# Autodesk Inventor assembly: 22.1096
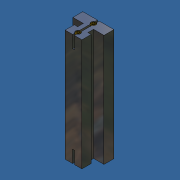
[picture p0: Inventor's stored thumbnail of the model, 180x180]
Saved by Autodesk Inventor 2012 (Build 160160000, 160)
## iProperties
Created: 2007-06
Part Number: 22.1096
Document SubType Name: Assembly
Designer: Andy Moles
Description: SLIDE RAIL LN-S
Vendor: S
Author: Andy Moles
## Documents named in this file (5)
- C:\Andys Backup Data\ANDY'S INVENTOR\INVENTOR LIBRARIES\PARTS LIBRARY\COMPONENTS LG\22.1096 SLIDE RAIL LN-S.iam
- C:\Andys Backup Data\ANDY'S INVENTOR\INVENTOR LIBRARIES\PARTS LIBRARY\COMPONENTS LG\SUBCOMPONENTS\22.1096_1 SLIDE RAIL LN-S SLIDE BAR.ipt
- C:\Andys Backup Data\ANDY'S INVENTOR\INVENTOR LIBRARIES\PARTS LIBRARY\COMPONENTS LG\SUBCOMPONENTS\22.1096 SLIDE RAIL LN-S THREAD INSERT.ipt
- C:\Andys Backup Data\ANDY'S INVENTOR\INVENTOR LIBRARIES\PARTS LIBRARY\FASTENING ELEMENTS\SET SCREWS\21.1314 M4x8 SET SCREW POINTED.IPT
- C:\Andys Backup Data\ANDY'S INVENTOR\INVENTOR LIBRARIES\PARTS LIBRARY\FASTENING ELEMENTS\SCREWS CAP\21.1229 M4x12.ipt
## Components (9 placed, 4 different names)
1. 22.1096_1 SLIDE RAIL LN-S SLIDE BAR:1 — Insert:2, Insert:3, Insert:4, Insert:5, Insert:6, Insert:9
2. 22.1096 SLIDE RAIL LN-S THREAD INSERT:1 — Insert:2, Insert:8
3. 22.1096 SLIDE RAIL LN-S THREAD INSERT:2 — Insert:7, Insert:9
4. 21.1314 M4X8 SET SCREW CONE POINT DIN 914:1 — Insert:3
5. 21.1314 M4X8 SET SCREW CONE POINT DIN 914:2 — Insert:4
6. 21.1314 M4X8 SET SCREW CONE POINT DIN 914:3 — Insert:5
7. 21.1314 M4X8 SET SCREW CONE POINT DIN 914:4 — Insert:6
8. 21.1229 SHCS M4X12 DIN 7984:1 — Insert:7
9. 21.1229 SHCS M4X12 DIN 7984:2 — Insert:8
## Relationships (8: Insert 8)
- Insert:2: 22.1096_1 SLIDE RAIL LN-S SLIDE BAR:1 ↔ 22.1096 SLIDE RAIL LN-S THREAD INSERT:1
- Insert:3: 22.1096_1 SLIDE RAIL LN-S SLIDE BAR:1 ↔ 21.1314 M4X8 SET SCREW CONE POINT DIN 914:1
- Insert:4: 22.1096_1 SLIDE RAIL LN-S SLIDE BAR:1 ↔ 21.1314 M4X8 SET SCREW CONE POINT DIN 914:2
- Insert:5: 22.1096_1 SLIDE RAIL LN-S SLIDE BAR:1 ↔ 21.1314 M4X8 SET SCREW CONE POINT DIN 914:3
- Insert:6: 22.1096_1 SLIDE RAIL LN-S SLIDE BAR:1 ↔ 21.1314 M4X8 SET SCREW CONE POINT DIN 914:4
- Insert:7: 22.1096 SLIDE RAIL LN-S THREAD INSERT:2 ↔ 21.1229 SHCS M4X12 DIN 7984:1
- Insert:8: 22.1096 SLIDE RAIL LN-S THREAD INSERT:1 ↔ 21.1229 SHCS M4X12 DIN 7984:2
- Insert:9: 22.1096_1 SLIDE RAIL LN-S SLIDE BAR:1 ↔ 22.1096 SLIDE RAIL LN-S THREAD INSERT:2
